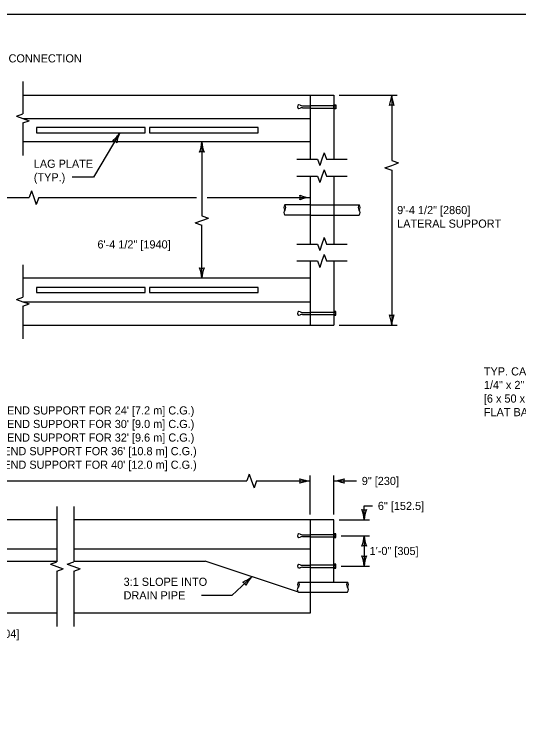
# Model space of a CAD drawing. Extents: x 49991.4 to 50021, y 49987.6 to 50011.4.
# Drawn here: x 50005.71 to 50009.43, y 49993.74 to 49999 of the extents above; entities that cross this region are included whole.
import ezdxf

# ---------------------------------------------------------------- set-up
doc = ezdxf.new("R2010")
doc.units = 0
for name, color, linetype in [('Level 1', 7, 'Continuous'), ('Level 2', 7, 'Continuous'), ('Level 3', 7, 'Continuous'), ('Level 4', 7, 'Continuous'), ('Level 5', 7, 'Continuous'), ('Level 6', 7, 'Continuous')]:
    doc.layers.add(name, color=color, linetype=linetype)

msp = doc.modelspace()

# ---------------------------------------------------------------- linework, layer by layer
at = {"layer": 'Level 1'}
for p, q in [((50005.7761, 49998.4043), (50008.0654, 49998.4043)), ((50007.8929, 49998.4043), (50007.8929, 49997.9317)), ((50008.0654, 49998.4043), (50008.0654, 49997.9317)), ((50008.0654, 49998.3251), (50008.0804, 49998.3251)), ((50008.0654, 49998.3109), (50008.0804, 49998.3109)), ((50005.7761, 49998.2318), (50007.8929, 49998.2318)), ((50006.6761, 49998.1646), (50005.876, 49998.1646)), ((50005.876, 49998.1646), (50005.876, 49998.1264)), ((50006.6761, 49998.1264), (50006.6761, 49998.1646)), ((50007.5095, 49998.1646), (50006.7094, 49998.1646)), ((50006.7094, 49998.1646), (50006.7094, 49998.1264)), ((50007.5095, 49998.1264), (50007.5095, 49998.1646)), ((50005.876, 49998.1264), (50006.6761, 49998.1264)), ((50006.7094, 49998.1264), (50007.5095, 49998.1264)), ((50007.8929, 49998.0593), (50005.7761, 49998.0593)), ((50007.8929, 49997.8067), (50007.8929, 49997.3067)), ((50008.0654, 49997.8067), (50008.0654, 49997.3067)), ((50007.8929, 49997.5942), (50007.7054, 49997.5942)), ((50008.0654, 49997.5942), (50008.2529, 49997.5942)), ((50007.8929, 49997.5192), (50007.7056, 49997.5192)), ((50008.0654, 49997.5192), (50008.2526, 49997.5192)), ((50007.8929, 49997.1817), (50007.8929, 49996.7092)), ((50008.0654, 49997.1817), (50008.0654, 49996.7092)), ((50007.8929, 49997.0542), (50005.7761, 49997.0542)), ((50006.6761, 49996.9871), (50005.876, 49996.9871)), ((50005.876, 49996.9871), (50005.876, 49996.9488)), ((50006.6761, 49996.9488), (50006.6761, 49996.9871)), ((50007.5095, 49996.9871), (50006.7094, 49996.9871)), ((50006.7094, 49996.9871), (50006.7094, 49996.9488)), ((50007.5095, 49996.9488), (50007.5095, 49996.9871)), ((50005.876, 49996.9488), (50006.6761, 49996.9488)), ((50006.7094, 49996.9488), (50007.5095, 49996.9488)), ((50005.7765, 49996.8817), (50007.8929, 49996.8817)), ((50008.0654, 49996.8026), (50008.0804, 49996.8026)), ((50008.0654, 49996.7883), (50008.0804, 49996.7883)), ((50005.7761, 49996.7092), (50008.0654, 49996.7092)), ((50006.0262, 49995.2739), (50003.6843, 49995.2739)), ((50007.8929, 49995.2739), (50006.1512, 49995.2739)), ((50007.8929, 49995.2739), (50007.8929, 49994.5876)), ((50008.0654, 49995.2739), (50007.8929, 49995.2739)), ((50008.0654, 49994.8164), (50008.0654, 49995.2739)), ((50008.0654, 49995.1648), (50008.0804, 49995.1648)), ((50008.0654, 49995.1505), (50008.0804, 49995.1505)), ((50008.0654, 49994.9397), (50008.0804, 49994.9397)), ((50008.0654, 49994.9255), (50008.0804, 49994.9255)), ((50007.8066, 49994.8164), (50007.8066, 49994.8164)), ((50007.8066, 49994.8164), (50007.9791, 49994.8164)), ((50007.8929, 49994.8164), (50008.0654, 49994.8164)), ((50007.9791, 49994.8164), (50008.1666, 49994.8164)), ((50007.8069, 49994.7414), (50007.8066, 49994.7414)), ((50007.8066, 49994.7414), (50007.9791, 49994.7414)), ((50007.9791, 49994.7414), (50008.1664, 49994.7414)), ((50006.0262, 49994.5876), (50003.6843, 49994.5876)), ((50007.8929, 49994.5876), (50006.1512, 49994.5876))]:
    msp.add_line(p, q, dxfattribs=at)
for points in [[(49999.3835, 49998.9992), (50016.7501, 49998.9992), (50016.7501, 49987.7988), (49999.3835, 49987.7988)], [(50008.0654, 49998.3323), (50008.0804, 49998.3323), (50008.0804, 49998.3038), (50008.0654, 49998.3038)], [(50008.0654, 49996.7812), (50008.0804, 49996.7812), (50008.0804, 49996.8097), (50008.0654, 49996.8097)], [(50008.0654, 49995.1434), (50008.0804, 49995.1434), (50008.0804, 49995.1719), (50008.0654, 49995.1719)], [(50008.0654, 49994.9184), (50008.0804, 49994.9184), (50008.0804, 49994.9469), (50008.0654, 49994.9469)]]:
    msp.add_lwpolyline(points, close=True, dxfattribs=at)
for centre, radius, start, end in [((50007.7263, 49997.5755), 0.0281, 138.1897, 221.8103), ((50007.6844, 49997.5755), 0.0281, 318.1897, 41.8103), ((50008.2738, 49997.5755), 0.0281, 138.1897, 221.8103), ((50008.2319, 49997.5755), 0.0281, 318.1897, 41.8103), ((50007.7259, 49997.5381), 0.0277, 137.8811, 222.9096), ((50008.232, 49997.5381), 0.0279, 317.445, 41.7642), ((50007.8213, 49994.7601), 0.0239, 128.1715, 231.8285), ((50007.8276, 49994.7976), 0.0281, 138.1897, 221.8103), ((50007.7856, 49994.7976), 0.0281, 318.1897, 41.8103), ((50008.1876, 49994.7976), 0.0281, 138.1897, 221.8103), ((50008.1458, 49994.7603), 0.0279, 317.3528, 41.8565), ((50008.1456, 49994.7976), 0.0281, 318.1897, 41.8103)]:
    msp.add_arc(centre, radius, start, end, dxfattribs=at)
at = {"layer": 'Level 3'}
for p, q in [((50008.1054, 49998.4043), (50008.5324, 49998.4043)), ((50008.4924, 49998.4043), (50008.4925, 49997.9215)), ((50006.4918, 49998.1264), (50006.2973, 49997.7981)), ((50007.0945, 49998.0593), (50007.0945, 49997.5154)), ((50008.4425, 49997.8684), (50008.4925, 49997.8861)), ((50008.4925, 49997.9215), (50008.5425, 49997.9038)), ((50008.4925, 49997.8861), (50008.5425, 49997.9038)), ((50008.4425, 49997.8684), (50008.4925, 49997.8506)), ((50008.4925, 49997.8506), (50008.4925, 49996.7092)), ((50006.2973, 49997.7981), (50006.1407, 49997.7981)), ((50005.8401, 49997.6988), (50005.8224, 49997.6488)), ((50005.8401, 49997.6988), (50005.8578, 49997.6488)), ((50003.5709, 49997.6488), (50005.8224, 49997.6488)), ((50005.8578, 49997.6488), (50005.8756, 49997.5988)), ((50005.8933, 49997.6488), (50005.8756, 49997.5988)), ((50005.8933, 49997.6488), (50007.0545, 49997.6488)), ((50007.1345, 49997.6488), (50007.8929, 49997.6488)), ((50007.0945, 49997.5154), (50007.1445, 49997.4977)), ((50007.0445, 49997.4622), (50007.0945, 49997.48)), ((50007.0445, 49997.4622), (50007.0945, 49997.4445)), ((50007.0945, 49997.48), (50007.1445, 49997.4977)), ((50007.0945, 49997.0542), (50007.0945, 49997.4445)), ((50008.1054, 49996.7092), (50008.5325, 49996.7092)), ((50007.4437, 49995.6107), (50007.426, 49995.5607)), ((50007.4437, 49995.6107), (50007.4614, 49995.5607)), ((50007.8932, 49995.3139), (50007.8932, 49995.6008)), ((50008.0657, 49995.3139), (50008.0657, 49995.6008)), ((50005.1745, 49995.5607), (50007.426, 49995.5607)), ((50007.4614, 49995.5607), (50007.4792, 49995.5107)), ((50007.4969, 49995.5607), (50007.4792, 49995.5107)), ((50007.4969, 49995.5607), (50007.8932, 49995.5608)), ((50008.0657, 49995.5608), (50008.2323, 49995.5608)), ((50008.2901, 49995.2739), (50008.2901, 49995.377)), ((50008.2901, 49995.377), (50008.3508, 49995.377)), ((50008.1054, 49995.2739), (50008.3301, 49995.2739)), ((50008.2901, 49995.1576), (50008.2901, 49994.9326)), ((50007.4635, 49994.8557), (50007.3155, 49994.7181)), ((50007.3155, 49994.7181), (50007.091, 49994.7181))]:
    msp.add_line(p, q, dxfattribs=at)
for centre, radius, start, end in [((50008.2703, 49998.4134), 0.2223, 337.456, 357.6395), ((50008.7252, 49998.4158), 0.233, 182.8273, 202.0772), ((50008.4924, 49998.276), 0.0548, 72.1388, 107.8612), ((50006.3054, 49998.2475), 0.2223, 306.8032, 326.9867), ((50006.6979, 49998.0176), 0.233, 152.1745, 171.4243), ((50006.4265, 49998.0161), 0.0548, 41.486, 77.2083), ((50006.8724, 49998.0684), 0.2223, 337.456, 357.6395), ((50007.3272, 49998.0707), 0.233, 182.8273, 202.0772), ((50007.0945, 49997.931), 0.0548, 72.1388, 107.8612), ((50007.902, 49997.8709), 0.2223, 247.456, 267.6395), ((50007.7647, 49997.6488), 0.0548, 342.1388, 17.8612), ((50007.9044, 49997.4161), 0.233, 92.8273, 112.0772), ((50007.0945, 49997.1824), 0.0548, 252.1388, 287.8612), ((50006.8618, 49997.0427), 0.233, 2.8273, 22.0772), ((50007.3167, 49997.0451), 0.2223, 157.456, 177.6395), ((50008.4925, 49996.8374), 0.0548, 252.1388, 287.8612), ((50008.2598, 49996.6977), 0.233, 2.8273, 22.0772), ((50008.7146, 49996.7001), 0.2223, 157.456, 177.6395), ((50007.9023, 49995.7829), 0.2223, 247.4637, 267.6472), ((50007.7649, 49995.5608), 0.0548, 342.1465, 17.8688), ((50008.0542, 49995.7935), 0.233, 272.8273, 292.0772), ((50008.1939, 49995.5608), 0.0548, 162.1388, 197.8612), ((50007.9047, 49995.3281), 0.233, 92.835, 112.0848), ((50008.0565, 49995.3386), 0.2223, 67.456, 87.6395), ((50008.2901, 49995.4021), 0.0548, 252.1388, 287.8612), ((50008.0574, 49995.2624), 0.233, 2.8273, 22.0772), ((50008.5122, 49995.2647), 0.2223, 157.456, 177.6395), ((50008.068, 49995.1668), 0.2223, 337.456, 357.6395), ((50008.5228, 49995.1691), 0.233, 182.8273, 202.0772), ((50008.2901, 49995.0294), 0.0548, 72.1388, 107.8612), ((50008.2901, 49995.0608), 0.0548, 252.1388, 287.8612), ((50008.0574, 49994.9211), 0.233, 2.8273, 22.0772), ((50008.5122, 49994.9235), 0.2223, 157.456, 177.6395), ((50007.3189, 49995.0246), 0.2223, 290.379, 310.5625), ((50007.6304, 49994.6932), 0.233, 135.7503, 155.0001), ((50007.3696, 49994.7684), 0.0548, 25.0618, 60.7842)]:
    msp.add_arc(centre, radius, start, end, dxfattribs=at)
at = {"layer": 'Level 4'}
for p, q in [((50007.8352, 49998.3251), (50007.8929, 49998.3251)), ((50007.8352, 49998.3109), (50007.8929, 49998.3109)), ((50007.8929, 49998.3274), (50008.0654, 49998.3274)), ((50007.8929, 49998.3086), (50008.0654, 49998.3086)), ((50007.8929, 49997.5942), (50008.0654, 49997.5942)), ((50007.8929, 49997.5192), (50008.0654, 49997.5192)), ((50007.8352, 49996.8026), (50007.8929, 49996.8026)), ((50007.8352, 49996.7883), (50007.8929, 49996.7883)), ((50007.8929, 49996.8048), (50008.0654, 49996.8048)), ((50007.8929, 49996.7861), (50008.0654, 49996.7861)), ((50007.8352, 49995.1648), (50007.8929, 49995.1648)), ((50007.8352, 49995.1505), (50007.8929, 49995.1505)), ((50007.8929, 49995.167), (50008.0654, 49995.167)), ((50007.8929, 49995.1483), (50008.0654, 49995.1483)), ((50005.2526, 49995.0601), (50006.0262, 49995.0601)), ((50006.1512, 49995.0601), (50007.8929, 49995.0601)), ((50003.6843, 49994.9701), (50006.0262, 49994.9701)), ((50006.1512, 49994.9701), (50007.1203, 49994.9701)), ((50007.8066, 49994.7414), (50007.1203, 49994.9701)), ((50007.8352, 49994.9397), (50007.8929, 49994.9397)), ((50007.8929, 49994.942), (50008.0654, 49994.942)), ((50007.8352, 49994.9255), (50007.8929, 49994.9255)), ((50007.8929, 49994.9232), (50008.0654, 49994.9232))]:
    msp.add_line(p, q, dxfattribs=at)
for centre, radius, start, end in [((50007.8122, 49998.318), 0.0131, 60.6919, 299.3081), ((50007.8352, 49998.3589), 0.0338, 240.6919, 270), ((50007.8352, 49998.2771), 0.0338, 90, 119.3081), ((50007.8122, 49998.318), 0.0131, 299.3081094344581, 299.3081113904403), ((50007.8122, 49996.7955), 0.0131, 60.6919, 299.3081), ((50007.8352, 49996.8363), 0.0338, 240.6919, 270), ((50007.8122, 49996.7955), 0.0131, 60.691888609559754, 60.69189056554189), ((50007.8352, 49996.7546), 0.0338, 90, 119.3081), ((50007.8122, 49995.1576), 0.0131, 60.6919, 299.3081), ((50007.8352, 49995.1985), 0.0338, 240.6919, 270), ((50007.8122, 49995.1576), 0.0131, 60.691888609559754, 60.69189056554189), ((50007.8352, 49995.1168), 0.0338, 90, 119.3081), ((50007.8122, 49994.9326), 0.0131, 60.6919, 299.3081), ((50007.8352, 49994.9735), 0.0338, 240.6919, 270), ((50007.8122, 49994.9326), 0.0131, 60.691888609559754, 60.69189056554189), ((50007.8352, 49994.8917), 0.0338, 90, 119.3081)]:
    msp.add_arc(centre, radius, start, end, dxfattribs=at)
at = {"layer": 'Level 5'}
for p, q in [((50008.1204, 49995.1576), (50008.3301, 49995.1576)), ((50008.1204, 49994.9326), (50008.3301, 49994.9326))]:
    msp.add_line(p, q, dxfattribs=at)
at = {"layer": 'Level 6'}
for p, q in [((50005.7761, 49998.5043), (50005.7761, 49998.2652)), ((50005.729, 49998.2485), (50005.7761, 49998.2652)), ((50005.729, 49998.2485), (50005.7761, 49998.2318)), ((50005.7761, 49998.2318), (50005.8232, 49998.2151)), ((50005.7761, 49998.1984), (50005.8232, 49998.2151)), ((50005.7761, 49998.1984), (50005.7761, 49997.9593)), ((50007.9958, 49997.9788), (50007.9791, 49997.9317)), ((50007.9958, 49997.9788), (50008.0125, 49997.9317)), ((50007.7929, 49997.9317), (50007.9457, 49997.9317)), ((50007.9457, 49997.9317), (50007.9624, 49997.8846)), ((50007.9791, 49997.9317), (50007.9624, 49997.8846)), ((50008.0125, 49997.9317), (50008.1654, 49997.9317)), ((50007.9958, 49997.8538), (50007.9791, 49997.8067)), ((50007.9958, 49997.8538), (50008.0125, 49997.8067)), ((50007.7929, 49997.8067), (50007.9457, 49997.8067)), ((50007.9457, 49997.8067), (50007.9624, 49997.7596)), ((50007.9791, 49997.8067), (50007.9624, 49997.7596)), ((50008.0125, 49997.8067), (50008.1654, 49997.8067)), ((50007.7929, 49997.3067), (50007.9457, 49997.3067)), ((50007.9457, 49997.3067), (50007.9624, 49997.2596)), ((50007.9791, 49997.3067), (50007.9624, 49997.2596)), ((50007.9958, 49997.3538), (50007.9791, 49997.3067)), ((50007.9958, 49997.3538), (50008.0125, 49997.3067)), ((50008.0125, 49997.3067), (50008.1654, 49997.3067)), ((50007.9958, 49997.2288), (50007.9791, 49997.1817)), ((50007.9958, 49997.2288), (50008.0125, 49997.1817)), ((50005.7761, 49997.1542), (50005.7761, 49996.9152)), ((50007.7929, 49997.1817), (50007.9457, 49997.1817)), ((50007.9457, 49997.1817), (50007.9624, 49997.1346)), ((50007.9791, 49997.1817), (50007.9624, 49997.1346)), ((50008.0125, 49997.1817), (50008.1654, 49997.1817)), ((50005.729, 49996.8985), (50005.7761, 49996.9152)), ((50005.729, 49996.8985), (50005.7761, 49996.8818)), ((50005.7761, 49996.8818), (50005.8232, 49996.8651)), ((50005.7761, 49996.8484), (50005.8232, 49996.8651)), ((50005.7761, 49996.8484), (50005.7761, 49996.6092)), ((50006.0262, 49995.3739), (50006.0262, 49994.9642)), ((50006.1512, 49995.3739), (50006.1512, 49994.9642)), ((50005.9791, 49994.9475), (50006.0262, 49994.9642)), ((50005.9791, 49994.9475), (50006.0262, 49994.9308)), ((50006.1041, 49994.9475), (50006.1512, 49994.9642)), ((50006.1041, 49994.9475), (50006.1512, 49994.9308)), ((50006.0262, 49994.9308), (50006.0733, 49994.9141)), ((50006.0262, 49994.8974), (50006.0733, 49994.9141)), ((50006.0262, 49994.8974), (50006.0262, 49994.4876)), ((50006.1512, 49994.9308), (50006.1983, 49994.9141)), ((50006.1512, 49994.8974), (50006.1983, 49994.9141)), ((50006.1512, 49994.8974), (50006.1512, 49994.4876))]:
    msp.add_line(p, q, dxfattribs=at)

# ---------------------------------------------------------------- texts
at = {"layer": 'Level 2'}
for s, p in [('SPLICE CONNECTION', (50005.3635, 49998.6445)), ('LAG PLATE', (50005.8571, 49997.8681)), ('(TYP.)', (50005.8571, 49997.7681)), ('9\'-4 1/2" [2860]', (50008.5325, 49997.5269)), ('LATERAL SUPPORT', (50008.5325, 49997.4269)), ('6\'-4 1/2" [1940]', (50006.326, 49997.2738)), ('TYP. CAST IN', (50009.1713, 49996.3382)), ('1/4" x 2" x 4\'-6"', (50009.1713, 49996.2382)), ('[6 x 50 x 1370]', (50009.1713, 49996.1382)), ('12\'-3" [3735] (END SUPPORT FOR 24\' [7.2 m] C.G.)', (50005.1609, 49996.0507)), ('FLAT BAR LAG PLATE', (50009.1713, 49996.0382)), ('15\'-3" [4650] (END SUPPORT FOR 30\' [9.0 m] C.G.)', (50005.1609, 49995.9507)), ('16\'-3" [4955] (END SUPPORT FOR 32\' [9.6 m] C.G.)', (50005.1609, 49995.8507)), ('18\'-3" [5565] (END SUPPORT FOR 36\' [10.8 m] C.G.)', (50005.134, 49995.7507)), ('20\'-3" [6175] (END SUPPORT FOR 40\' [12.0 m] C.G.)', (50005.134, 49995.6507)), ('9" [230]', (50008.2723, 49995.5308)), ('6" [152.5]', (50008.3908, 49995.347)), ('1\'-0" [305]', (50008.3301, 49995.0151)), ('3:1 SLOPE INTO', (50006.5184, 49994.7881)), ('DRAIN PIPE', (50006.5184, 49994.6881)), ('8" [204]', (50005.4769, 49994.4053))]:
    msp.add_text(s, height=0.06, dxfattribs=at).set_placement(p)

doc.saveas('drawing.dxf')
